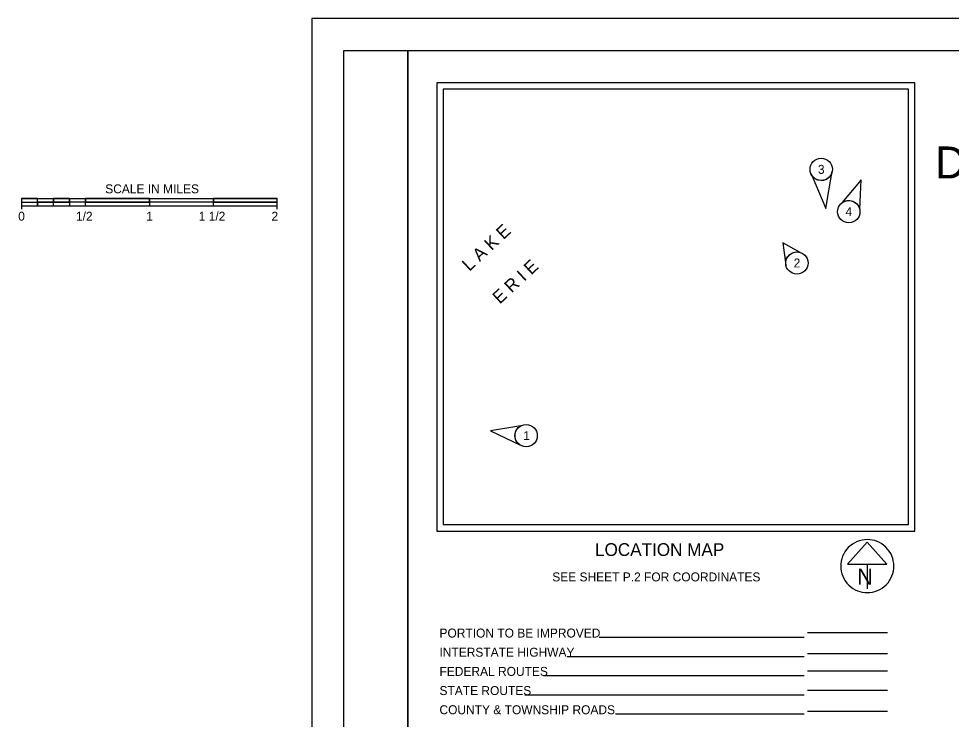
# Model space of a CAD drawing. Extents: x -8.3 to 34, y 0 to 22.
# Drawn here: x -4.59 to 10, y 11.04 to 22 of the extents above; entities that cross this region are included whole.
import ezdxf

# ---------------------------------------------------------------- set-up
doc = ezdxf.new("R2010")
doc.units = 0
for name, color, linetype in [('GM_X_Minor_River_Text', 7, 'Continuous'), ('SH_Border', 7, 'Continuous'), ('SH_Cut_Line', 7, 'Continuous'), ('SH_Data', 7, 'Continuous'), ('SH_Text', 7, 'Continuous')]:
    doc.layers.add(name, color=color, linetype=linetype)

msp = doc.modelspace()

# ---------------------------------------------------------------- linework, layer by layer
at = {"layer": 'SH_Border'}
for points in [[(0.5, 21.5), (1.5, 21.5), (1.5, 0.5), (0.5, 0.5)], [(1.5, 21.5), (33.5, 21.5), (33.5, 0.5), (1.5, 0.5)]]:
    msp.add_lwpolyline(points, close=True, dxfattribs=at)
at = {"layer": 'SH_Cut_Line'}
msp.add_lwpolyline([(0, 0), (34, 0), (34, 22), (0, 22)], close=True, dxfattribs=at)
at = {"layer": 'SH_Data'}
for p, q in [((-4.543, 19.184), (-4.543, 19.022)), ((-4.543, 19.184), (-0.543, 19.184)), ((-4.543, 19.128), (-4.293, 19.128)), ((-4.293, 19.072), (-4.293, 19.184)), ((-4.293, 19.128), (-4.043, 19.128)), ((-4.043, 19.072), (-4.043, 19.184)), ((-3.793, 19.128), (-4.043, 19.128)), ((-3.793, 19.184), (-3.793, 19.072)), ((-3.543, 19.128), (-3.793, 19.128)), ((-3.543, 19.072), (-3.543, 19.184)), ((-2.543, 19.128), (-3.543, 19.128)), ((-2.543, 19.184), (-2.543, 19.072)), ((-1.543, 19.128), (-2.543, 19.128)), ((-1.543, 19.072), (-1.543, 19.184)), ((-0.543, 19.128), (-1.543, 19.128)), ((-0.543, 19.022), (-0.543, 19.184)), ((-4.543, 19.072), (-0.543, 19.072)), ((2.155, 14.1), (2.155, 14.1)), ((8.685, 13.809), (8.377, 13.468)), ((8.992, 13.468), (8.685, 13.809)), ((8.377, 13.468), (8.992, 13.468)), ((8.685, 13.468), (8.685, 13.081)), ((8.685, 13.435), (8.685, 13.435)), ((8.685, 13.435), (8.685, 13.435)), ((7.7, 12.318), (4.494, 12.318)), ((7.75, 12.396), (9, 12.396)), ((7.7, 12.018), (3.99, 12.018)), ((9, 12.062), (7.75, 12.062)), ((7.7, 11.718), (3.619, 11.718)), ((9, 11.79), (7.75, 11.79)), ((7.7, 11.418), (3.329, 11.418)), ((9, 11.49), (7.75, 11.49)), ((7.7, 11.118), (4.745, 11.118)), ((9, 11.163), (7.75, 11.163))]:
    msp.add_line(p, q, dxfattribs=at)
for points in [[(1.951, 13.984), (9.43, 13.984), (9.43, 20.998), (1.951, 20.998)], [(2.051, 14.084), (9.33, 14.084), (9.33, 20.898), (2.051, 20.898)], [(-4.543, 19.184), (-4.543, 19.128), (-4.293, 19.128), (-4.293, 19.184)], [(-4.293, 19.072), (-4.043, 19.072), (-4.043, 19.128), (-4.293, 19.128)], [(-4.043, 19.184), (-4.043, 19.128), (-3.793, 19.128), (-3.793, 19.184)], [(-3.793, 19.072), (-3.543, 19.072), (-3.543, 19.128), (-3.793, 19.128)], [(-3.543, 19.184), (-3.543, 19.128), (-2.543, 19.128), (-2.543, 19.184)], [(-2.543, 19.072), (-1.543, 19.072), (-1.543, 19.128), (-2.543, 19.128)], [(-0.543, 19.184), (-1.543, 19.184), (-1.543, 19.128), (-0.543, 19.128)]]:
    msp.add_lwpolyline(points, close=True, dxfattribs=at)
msp.add_arc((8.685, 13.435), 0.415, 129.7798, 129.7633, dxfattribs=at)
at = {"layer": 'SH_Text'}
for points in [[(7.85, 19.51), (7.818, 19.548), (7.805, 19.572), (8.039, 19.028), (8.138, 19.614), (8.124, 19.569), (8.108, 19.541), (8.086, 19.515), (8.046, 19.486), (8.001, 19.47), (7.961, 19.467), (7.914, 19.474), (7.881, 19.488)], [(8.517, 19.107), (8.55, 19.064), (8.568, 19.017), (8.59, 19.478), (8.289, 19.118), (8.326, 19.141), (8.372, 19.153), (8.411, 19.155), (8.459, 19.142), (8.492, 19.125)], [(7.533, 18.344), (7.586, 18.352), (7.636, 18.344), (7.364, 18.494), (7.413, 18.145), (7.411, 18.194), (7.421, 18.24), (7.44, 18.275), (7.475, 18.31), (7.505, 18.331)], [(3.195, 15.558), (3.227, 15.602), (3.269, 15.631), (2.792, 15.554), (3.249, 15.333), (3.213, 15.366), (3.188, 15.406), (3.177, 15.445), (3.177, 15.494), (3.184, 15.53)]]:
    msp.add_lwpolyline(points, close=True, dxfattribs=at)
for centre in [(7.965, 19.642), (8.396, 18.98), (7.585, 18.177), (3.349, 15.476)]:
    msp.add_circle(centre, 0.175, dxfattribs=at)

# ---------------------------------------------------------------- texts
at = {"layer": 'GM_X_Minor_River_Text'}
for s, p in [('L A K E', (2.461, 18.038)), ('E R I E', (2.938, 17.526))]:
    msp.add_text(s, height=0.2, rotation=42.9802, dxfattribs=at).set_placement(p)
at = {"layer": 'SH_Data'}
for s, height, p in [('SCALE IN MILES', 0.14, (-3.234, 19.267)), ('0', 0.14, (-4.595, 18.839)), ('1/2', 0.14, (-3.692, 18.839)), ('1', 0.14, (-2.593, 18.839)), ('1 1/2', 0.14, (-1.772, 18.839)), ('2', 0.14, (-0.633, 18.839)), ('N', 0.25, (8.529, 13.144))]:
    msp.add_text(s, height=height, dxfattribs=at).set_placement(p)
at = {"layer": 'SH_Text'}
for s, height, p in [('DEPARTMENT OF TRANSPORTATION', 0.5, (9.747, 19.5)), ('3', 0.14, (7.913, 19.572)), ('4', 0.14, (8.344, 18.91)), ('2', 0.14, (7.533, 18.107)), ('1', 0.14, (3.303, 15.406)), ('LOCATION MAP', 0.2, (4.427, 13.594)), ('SEE SHEET P.2 FOR COORDINATES', 0.14, (3.758, 13.196)), ('PORTION TO BE IMPROVED', 0.14, (1.994, 12.318)), ('INTERSTATE HIGHWAY', 0.14, (1.994, 12.018)), ('FEDERAL ROUTES', 0.14, (1.994, 11.718)), ('STATE ROUTES', 0.14, (1.994, 11.418)), ('COUNTY & TOWNSHIP ROADS', 0.14, (1.994, 11.118))]:
    msp.add_text(s, height=height, dxfattribs=at).set_placement(p)

doc.saveas('drawing.dxf')
